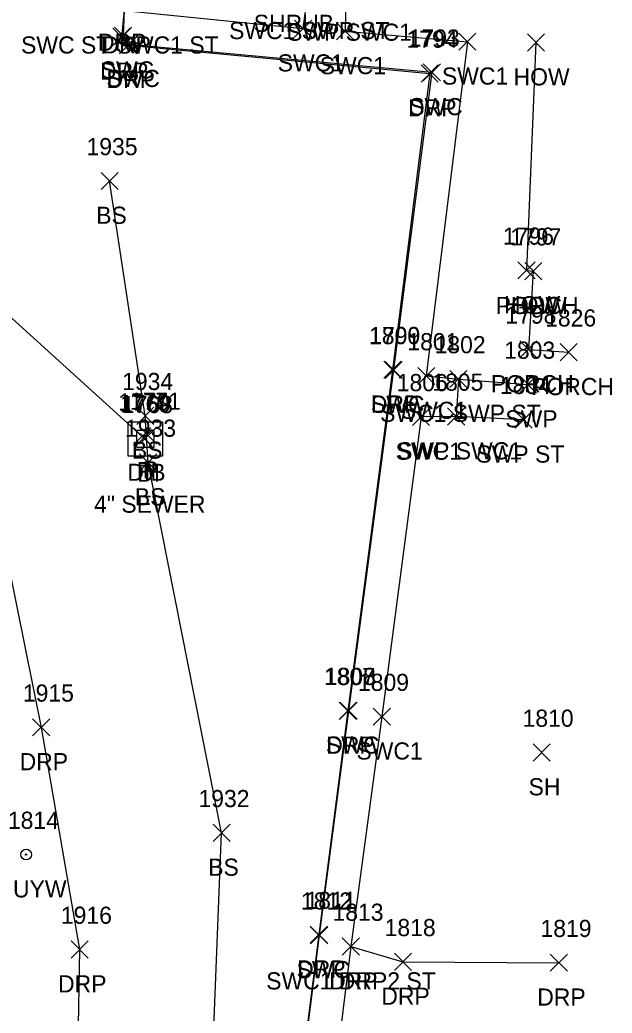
# Model space of a CAD drawing. Extents: x 1651305 to 1654558, y 539481 to 548441.
# Drawn here: x 1654395.2 to 1654464.3, y 544544.9 to 544660.7 of the extents above; entities that cross this region are included whole.
import ezdxf

# ---------------------------------------------------------------- set-up
doc = ezdxf.new("R2010")
doc.units = 0
for name, color, linetype in [('D_A', 7, 'Continuous'), ('D_C', 7, 'Continuous'), ('D_I', 7, 'Continuous'), ('D_TIC', 7, 'Continuous'), ('DCP', 7, 'Continuous'), ('DS', 7, 'Continuous'), ('L_A', 7, 'Continuous'), ('L_I', 7, 'Continuous'), ('L_TIC', 7, 'Continuous'), ('LBC', 7, 'Continuous'), ('LBF', 7, 'Continuous'), ('LELB', 7, 'Continuous'), ('R_A', 7, 'Continuous'), ('R_I', 7, 'Continuous'), ('R_TIC', 7, 'Continuous'), ('RDP', 7, 'Continuous'), ('RSW', 7, 'Continuous'), ('U_A', 7, 'Continuous'), ('U_I', 7, 'Continuous'), ('UPGW', 7, 'Continuous')]:
    doc.layers.add(name, color=color, linetype=linetype)

msp = doc.modelspace()

# ---------------------------------------------------------------- linework, layer by layer
at = {"layer": 'D_TIC'}
for points in [[(1654408.49, 544611.15), (1654410.49, 544613.15)], [(1654410.49, 544611.15), (1654408.49, 544613.15)], [(1654408.67, 544610.97), (1654410.67, 544612.97)], [(1654410.67, 544610.97), (1654408.67, 544612.97)], [(1654409.2, 544611.25), (1654411.2, 544613.25)], [(1654411.2, 544611.25), (1654409.2, 544613.25)]]:
    msp.add_lwpolyline(points, dxfattribs=at)
at = {"layer": 'DCP'}
msp.add_lwpolyline([(1654358.09, 544658.76), (1654409.49, 544612.15)], dxfattribs=at)
at = {"layer": 'DS'}
for p, q in [((1654407.86, 544613.86), (1654411.86, 544613.86)), ((1654407.86, 544609.86), (1654407.86, 544613.86)), ((1654411.86, 544613.86), (1654411.86, 544609.86)), ((1654408.86, 544610.86), (1654408.86, 544612.86)), ((1654408.86, 544612.86), (1654410.86, 544612.86)), ((1654410.86, 544612.86), (1654410.86, 544610.86)), ((1654409.87, 544611.86), (1654409.87, 544611.86)), ((1654409.87, 544611.86), (1654409.87, 544611.86)), ((1654410.86, 544610.86), (1654408.86, 544610.86)), ((1654411.86, 544609.86), (1654407.86, 544609.86))]:
    msp.add_line(p, q, dxfattribs=at)
at = {"layer": 'L_TIC'}
for points in [[(1654454.41, 544657.06), (1654456.41, 544659.06)], [(1654456.41, 544657.06), (1654454.41, 544659.06)], [(1654404.7, 544640.93), (1654406.7, 544642.93)], [(1654406.7, 544640.93), (1654404.7, 544642.93)], [(1654453.31, 544630.5), (1654455.31, 544632.5)], [(1654455.31, 544630.5), (1654453.31, 544632.5)], [(1654454.1, 544630.41), (1654456.1, 544632.41)], [(1654456.1, 544630.41), (1654454.1, 544632.41)], [(1654454.1, 544630.41), (1654456.1, 544632.41)], [(1654456.1, 544630.41), (1654454.1, 544632.41)], [(1654453.53, 544621.29), (1654455.53, 544623.29)], [(1654455.53, 544621.29), (1654453.53, 544623.29)], [(1654458.23, 544620.96), (1654460.23, 544622.96)], [(1654460.23, 544620.96), (1654458.23, 544622.96)], [(1654408.86, 544613.55), (1654410.86, 544615.55)], [(1654410.86, 544613.55), (1654408.86, 544615.55)], [(1654409.2, 544608.11), (1654411.2, 544610.11)], [(1654411.2, 544608.11), (1654409.2, 544610.11)], [(1654455.07, 544574.3), (1654457.07, 544576.3)], [(1654457.07, 544574.3), (1654455.07, 544576.3)], [(1654417.76, 544564.93), (1654419.76, 544566.93)], [(1654419.76, 544564.93), (1654417.76, 544566.93)]]:
    msp.add_lwpolyline(points, dxfattribs=at)
at = {"layer": 'LBC'}
msp.add_lwpolyline([(1654455.41, 544658.06), (1654454.31, 544631.5), (1654455.1, 544631.41)], dxfattribs=at)
at = {"layer": 'LBF'}
msp.add_lwpolyline([(1654455.1, 544631.41), (1654454.53, 544622.29), (1654459.23, 544621.96)], dxfattribs=at)
at = {"layer": 'LELB'}
msp.add_lwpolyline([(1654406.95, 544466.69), (1654414, 544500.45), (1654417.58, 544536.28), (1654418.76, 544565.93), (1654410.2, 544609.11), (1654409.86, 544614.55), (1654405.7, 544641.93)], dxfattribs=at)
at = {"layer": 'R_TIC'}
for points in [[(1654427.26, 544658.69), (1654429.26, 544660.69)], [(1654429.26, 544658.69), (1654427.26, 544660.69)], [(1654432.16, 544658.37), (1654434.16, 544660.37)], [(1654434.16, 544658.37), (1654432.16, 544660.37)], [(1654406.09, 544657.72), (1654408.09, 544659.72)], [(1654408.09, 544657.72), (1654406.09, 544659.72)], [(1654406.29, 544657.87), (1654408.29, 544659.87)], [(1654408.29, 544657.87), (1654406.29, 544659.87)], [(1654406.96, 544656.88), (1654408.96, 544658.88)], [(1654408.96, 544656.88), (1654406.96, 544658.88)], [(1654446.41, 544657.16), (1654448.41, 544659.16)], [(1654448.41, 544657.16), (1654446.41, 544659.16)], [(1654406.86, 544656.75), (1654408.86, 544658.75)], [(1654408.86, 544656.75), (1654406.86, 544658.75)], [(1654442.02, 544653.45), (1654444.02, 544655.45)], [(1654444.02, 544653.45), (1654442.02, 544655.45)], [(1654442.27, 544653.59), (1654444.27, 544655.59)], [(1654444.27, 544653.59), (1654442.27, 544655.59)], [(1654437.68, 544618.92), (1654439.68, 544620.92)], [(1654439.68, 544618.92), (1654437.68, 544620.92)], [(1654437.81, 544618.89), (1654439.81, 544620.89)], [(1654439.81, 544618.89), (1654437.81, 544620.89)], [(1654441.62, 544618.19), (1654443.62, 544620.19)], [(1654443.62, 544618.19), (1654441.62, 544620.19)], [(1654445.36, 544617.84), (1654447.36, 544619.84)], [(1654447.36, 544617.84), (1654445.36, 544619.84)], [(1654445.36, 544617.84), (1654447.36, 544619.84)], [(1654447.36, 544617.84), (1654445.36, 544619.84)], [(1654453.48, 544617.2), (1654455.48, 544619.2)], [(1654455.48, 544617.2), (1654453.48, 544619.2)], [(1654441.01, 544613.42), (1654443.01, 544615.42)], [(1654443.01, 544613.42), (1654441.01, 544615.42)], [(1654445.1, 544613.47), (1654447.1, 544615.47)], [(1654447.1, 544613.47), (1654445.1, 544615.47)], [(1654445.1, 544613.47), (1654447.1, 544615.47)], [(1654447.1, 544613.47), (1654445.1, 544615.47)], [(1654452.98, 544613.09), (1654454.98, 544615.09)], [(1654454.98, 544613.09), (1654452.98, 544615.09)], [(1654432.47, 544579.16), (1654434.47, 544581.16)], [(1654434.47, 544579.16), (1654432.47, 544581.16)], [(1654432.56, 544579.17), (1654434.56, 544581.17)], [(1654434.56, 544579.17), (1654432.56, 544581.17)], [(1654436.44, 544578.48), (1654438.44, 544580.48)], [(1654438.44, 544578.48), (1654436.44, 544580.48)], [(1654396.72, 544577.23), (1654398.72, 544579.23)], [(1654398.72, 544577.23), (1654396.72, 544579.23)], [(1654429.09, 544553.07), (1654431.09, 544555.07)], [(1654431.09, 544553.07), (1654429.09, 544555.07)], [(1654429.14, 544552.99), (1654431.14, 544554.99)], [(1654431.14, 544552.99), (1654429.14, 544554.99)], [(1654432.82, 544551.68), (1654434.82, 544553.68)], [(1654434.82, 544551.68), (1654432.82, 544553.68)], [(1654432.82, 544551.68), (1654434.82, 544553.68)], [(1654434.82, 544551.68), (1654432.82, 544553.68)], [(1654401.2, 544551.33), (1654403.2, 544553.33)], [(1654403.2, 544551.33), (1654401.2, 544553.33)], [(1654438.9, 544549.89), (1654440.9, 544551.89)], [(1654440.9, 544549.89), (1654438.9, 544551.89)], [(1654457.07, 544549.79), (1654459.07, 544551.79)], [(1654459.07, 544549.79), (1654457.07, 544551.79)]]:
    msp.add_lwpolyline(points, dxfattribs=at)
at = {"layer": 'RDP'}
for points in [[(1654389.4, 544756.56), (1654387.7, 544737.06), (1654385.3, 544704.99), (1654383.54, 544677.64), (1654384.48, 544660.97), (1654386.24, 544638.22), (1654391.02, 544611.18), (1654397.72, 544578.23), (1654402.2, 544552.33), (1654401.97, 544539.05), (1654399.16, 544531.47), (1654397.05, 544530.18)], [(1654432.45, 544721.26), (1654412.47, 544723.07), (1654409.32, 544720.53), (1654406.19, 544714.27), (1654402.61, 544671.58), (1654403.27, 544666.41), (1654406.85, 544662.1), (1654407.38, 544661.79), (1654407.09, 544658.72), (1654407.86, 544657.75), (1654443.02, 544654.45), (1654438.68, 544619.92), (1654433.47, 544580.16), (1654430.09, 544554.07), (1654427.97, 544537.22), (1654424.62, 544512.8), (1654419.65, 544473.55), (1654406.95, 544466.69)], [(1654433.82, 544552.68), (1654439.9, 544550.89), (1654458.07, 544550.79)]]:
    msp.add_lwpolyline(points, dxfattribs=at)
at = {"layer": 'RSW'}
for points in [[(1654407.4, 544661.78), (1654428.26, 544659.69), (1654428.76, 544663.46), (1654433.26, 544663.27), (1654433.16, 544659.37), (1654447.41, 544658.16), (1654442.62, 544619.19), (1654446.36, 544618.84), (1654446.1, 544614.47), (1654442.01, 544614.42), (1654437.44, 544579.48), (1654433.82, 544552.68), (1654432, 544537.93), (1654429.1, 544516.84), (1654432.21, 544516.45), (1654440.59, 544515.61)], [(1654407.4, 544661.78), (1654407.29, 544658.87), (1654407.96, 544657.88), (1654443.27, 544654.59), (1654438.81, 544619.89), (1654433.56, 544580.17), (1654430.14, 544553.99), (1654428.03, 544537.28), (1654424.83, 544512.84), (1654419.77, 544473.61), (1654412.66, 544419.66), (1654404.12, 544354.77), (1654402.1, 544339.77), (1654395.49, 544286.06), (1654394.01, 544276.12), (1654388.39, 544229.58), (1654383.89, 544196.38), (1654382.2, 544184.33), (1654378.35, 544149.15), (1654372.36, 544105.49), (1654368.55, 544072.05)], [(1654446.36, 544618.84), (1654454.48, 544618.2)], [(1654453.98, 544614.09), (1654446.1, 544614.47)]]:
    msp.add_lwpolyline(points, dxfattribs=at)
at = {"layer": 'UPGW'}
for radius in [0.625, 0.0833]:
    msp.add_circle((1654395.97, 544563.4), radius, dxfattribs=at)

# ---------------------------------------------------------------- texts
at = {"layer": 'D_A'}
for s, p in [('P', (1654408.87, 544607.15)), ('P', (1654409.58, 544607.25)), ('DIB', (1654407.77, 544606.97)), ('DI', (1654408.92, 544606.86))]:
    msp.add_text(s, height=2, dxfattribs=at).set_placement(p)
at = {"layer": 'D_C'}
msp.add_text('4" SEWER', height=2, dxfattribs=at).set_placement((1654403.89, 544603.25))
at = {"layer": 'D_I'}
for s, p in [('1770', (1654406.71, 544615.15)), ('1771', (1654408.07, 544615.25)), ('1769', (1654406.92, 544614.97)), ('1768', (1654407.13, 544614.86))]:
    msp.add_text(s, height=2, dxfattribs=at).set_placement(p)
at = {"layer": 'L_A'}
for s, p in [('SHRUB', (1654422.51, 544659.3)), ('HOW', (1654452.8, 544653.06)), ('BS', (1654404.14, 544636.93)), ('PORCH', (1654450.72, 544626.41)), ('HOW', (1654451.69, 544626.5)), ('HOW', (1654452.49, 544626.41)), ('PORCH', (1654450.16, 544617.29)), ('PORCH', (1654454.85, 544616.96)), ('BS', (1654408.3, 544609.55)), ('BS', (1654408.64, 544604.11)), ('SH', (1654454.55, 544570.3)), ('BS', (1654417.2, 544560.93))]:
    msp.add_text(s, height=2, dxfattribs=at).set_placement(p)
at = {"layer": 'L_I'}
for s, p in [('1935', (1654403.01, 544644.93)), ('1796', (1654451.56, 544634.5)), ('1797', (1654452.41, 544634.41)), ('1797', (1654452.41, 544634.41)), ('1798', (1654451.84, 544625.29)), ('1826', (1654456.48, 544624.96)), ('1934', (1654407.16, 544617.55)), ('1933', (1654407.5, 544612.11)), ('1810', (1654453.85, 544578.3)), ('1932', (1654416.06, 544568.93))]:
    msp.add_text(s, height=2, dxfattribs=at).set_placement(p)
at = {"layer": 'R_A'}
for s, p in [('SWC1 SWP ST', (1654419.63, 544658.46)), ('SWC1 SWP ST', (1654419.63, 544658.46)), ('SWP SWC1', (1654426.39, 544658.27)), ('SWP SWC1', (1654426.39, 544658.27)), ('DRP', (1654404.34, 544657.1)), ('SWC ST SWC1 ST', (1654395.38, 544656.78)), ('SWC ST SWC1 ST', (1654395.38, 544656.78)), ('DRP', (1654404.87, 544656.79)), ('SWC1', (1654425.3, 544654.69)), ('SWC', (1654404.66, 544653.87)), ('DRP', (1654404.58, 544653.72)), ('SWC1', (1654430.2, 544654.37)), ('SWC', (1654405.32, 544652.88)), ('DRP', (1654405.34, 544652.75)), ('SWC1', (1654444.45, 544653.16)), ('DRP', (1654440.5, 544649.45)), ('SWC', (1654440.63, 544649.59)), ('SWC', (1654436.17, 544614.89)), ('DRP', (1654436.16, 544614.92)), ('SWC1', (1654439.66, 544614.19)), ('SWC1 SWP ST', (1654437.24, 544613.84)), ('SWC1 SWP ST', (1654437.24, 544613.84)), ('SWP', (1654451.84, 544613.2)), ('SWC1', (1654439.05, 544609.42)), ('SWP SWC1', (1654439.23, 544609.47)), ('SWP SWC1', (1654439.23, 544609.47)), ('SWP ST', (1654448.47, 544609.09)), ('SWC', (1654430.92, 544575.17)), ('DRP', (1654430.96, 544575.16)), ('SWC1', (1654434.48, 544574.48)), ('DRP', (1654395.21, 544573.23)), ('SWC', (1654427.5, 544548.99)), ('DRP', (1654427.57, 544549.07)), ('DRP', (1654399.69, 544547.33)), ('SWC1 DRP2 ST', (1654423.96, 544547.68)), ('DRP', (1654431.3, 544547.68)), ('DRP', (1654437.38, 544545.89)), ('DRP', (1654455.56, 544545.79))]:
    msp.add_text(s, height=2, dxfattribs=at).set_placement(p)
at = {"layer": 'R_I'}
for s, p in [('1794', (1654440.32, 544657.45)), ('1793', (1654440.58, 544657.59)), ('1800', (1654435.95, 544622.89)), ('1799', (1654435.98, 544622.92)), ('1801', (1654440.42, 544622.19)), ('1802', (1654443.59, 544621.84)), ('1802', (1654443.59, 544621.84)), ('1803', (1654451.7, 544621.2)), ('1806', (1654439.18, 544617.42)), ('1805', (1654443.33, 544617.47)), ('1805', (1654443.33, 544617.47)), ('1804', (1654451.2, 544617.09)), ('1807', (1654430.7, 544583.16)), ('1808', (1654430.79, 544583.17)), ('1809', (1654434.66, 544582.48)), ('1915', (1654395.59, 544581.23)), ('1812', (1654428.01, 544556.99)), ('1811', (1654428.53, 544557.07)), ('1916', (1654400.02, 544555.33)), ('1813', (1654431.69, 544555.68)), ('1813', (1654431.69, 544555.68)), ('1818', (1654437.77, 544553.89)), ('1819', (1654455.94, 544553.79))]:
    msp.add_text(s, height=2, dxfattribs=at).set_placement(p)
at = {"layer": 'U_A'}
msp.add_text('GUYW', height=2, dxfattribs=at).set_placement((1654392.36, 544558.4))
at = {"layer": 'U_I'}
msp.add_text('1814', height=2, dxfattribs=at).set_placement((1654393.84, 544566.4))

doc.saveas('drawing.dxf')
